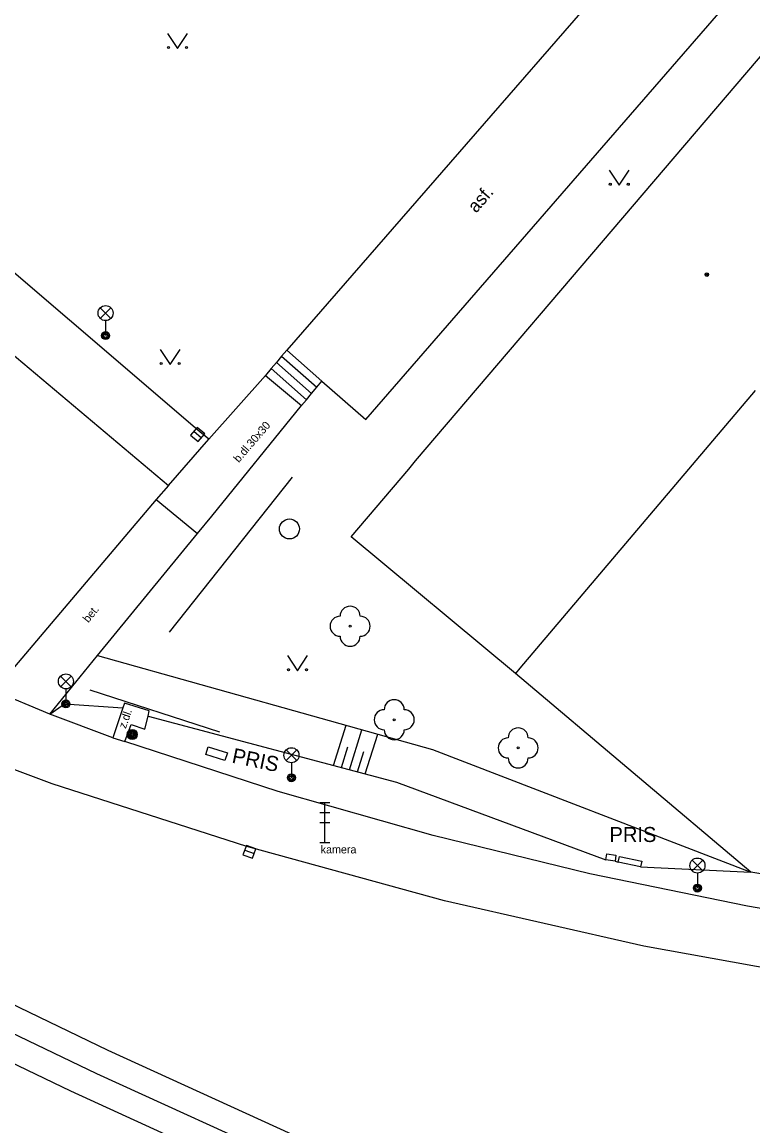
# Model space of a CAD drawing. Extents: x -598932 to -598196, y -1162207 to -1161504.
# Drawn here: x -598545.9 to -598509.4, y -1161999.2 to -1161944.1 of the extents above; entities that cross this region are included whole.
import ezdxf

# ---------------------------------------------------------------- set-up
doc = ezdxf.new("R2010")
doc.units = 0
for name, color, linetype in [('Level 22', 7, 'Continuous'), ('Level 25', 7, 'Continuous'), ('Level 27', 7, 'Continuous'), ('Level 33', 7, 'Continuous'), ('Level 36', 7, 'Continuous'), ('Level 39', 7, 'Continuous'), ('silnoproud - povrch.  znaky a  RIS  skut. velikost', 7, 'Continuous'), ('TM - budovy zdene_ betonove - VP', 7, 'Continuous'), ('TM - CD - osa koleji', 7, 'Continuous'), ('TM - chodniky - VP', 7, 'Continuous'), ('TM - dolni hrana svahu', 7, 'Continuous'), ('TM - horni hrana svahu', 7, 'Continuous'), ('TM - komunikace - VP', 7, 'Continuous'), ('TM - plot zdeny_ ohradni zed - VP', 7, 'Continuous'), ('TM - plot zivy neuzavreny', 7, 'Continuous'), ('TM - popis objektu', 7, 'Continuous'), ('TM - popis povrchu', 7, 'Continuous'), ('TM - poznamka', 7, 'Continuous'), ('TM - rozhrani mezi zpev. plochami mezi sebou - VP', 7, 'Continuous'), ('TM - rozhrani ploch obecne - VP', 7, 'Continuous'), ('TM - schody - VP', 7, 'Continuous'), ('TM - srafovani', 7, 'Continuous')]:
    doc.layers.add(name, color=color, linetype=linetype)

msp = doc.modelspace()

# ---------------------------------------------------------------- linework, layer by layer
at = {"layer": 'Level 22'}
for centre in [(-598529.55, -1161974.25), (-598527.35, -1161978.92), (-598521.16, -1161980.33)]:
    msp.add_circle(centre, 0.05, dxfattribs=at)
for centre, start, end in [((-598529.55, -1161973.75), 0, 180), ((-598530.05, -1161974.25), 90, 270), ((-598529.05, -1161974.25), 270, 90), ((-598529.55, -1161974.75), 180, 0), ((-598527.35, -1161978.42), 0, 180), ((-598527.85, -1161978.92), 90, 270), ((-598526.85, -1161978.92), 270, 90), ((-598527.35, -1161979.42), 180, 0), ((-598521.16, -1161979.83), 0, 180), ((-598521.66, -1161980.33), 90, 270), ((-598520.66, -1161980.33), 270, 90), ((-598521.16, -1161980.83), 180, 0)]:
    msp.add_arc(centre, 0.5, start, end, dxfattribs=at)
at = {"layer": 'Level 25'}
for radius in [0.25, 0.2, 0.15, 0.1, 0.05]:
    msp.add_circle((-598540.43, -1161979.66), radius, dxfattribs=at)
at = {"layer": 'Level 27'}
for p, q in [((-598537.351, -1161964.508), (-598536.969, -1161964.832)), ((-598534.815, -1161985.436), (-598534.345, -1161985.604))]:
    msp.add_line(p, q, dxfattribs=at)
for points in [[(-598537.512, -1161964.699), (-598537.131, -1161965.022), (-598536.808, -1161964.641), (-598537.189, -1161964.318)], [(-598534.899, -1161985.671), (-598534.429, -1161985.839), (-598534.261, -1161985.369), (-598534.731, -1161985.201)]]:
    msp.add_lwpolyline(points, close=True, dxfattribs=at)
msp.add_circle((-598532.58, -1161969.39), 0.5, dxfattribs=at)
at = {"layer": 'Level 33'}
for p, q in [((-598542.025, -1161958.87), (-598541.495, -1161958.34)), ((-598542.025, -1161958.34), (-598541.495, -1161958.87)), ((-598541.76, -1161958.98), (-598541.76, -1161959.73)), ((-598544.005, -1161977.27), (-598543.475, -1161976.74)), ((-598544.005, -1161976.74), (-598543.475, -1161977.27)), ((-598543.74, -1161977.38), (-598543.74, -1161978.13)), ((-598532.745, -1161980.96), (-598532.215, -1161980.43)), ((-598532.745, -1161980.43), (-598532.215, -1161980.96)), ((-598532.48, -1161981.07), (-598532.48, -1161981.82)), ((-598531.07, -1161983.05), (-598530.57, -1161983.05)), ((-598530.82, -1161985.05), (-598530.82, -1161983.05)), ((-598531.07, -1161983.55), (-598530.57, -1161983.55)), ((-598531.07, -1161984.05), (-598530.57, -1161984.05)), ((-598531.07, -1161985.05), (-598530.57, -1161985.05)), ((-598512.475, -1161986.47), (-598511.945, -1161985.94)), ((-598512.475, -1161985.94), (-598511.945, -1161986.47)), ((-598512.21, -1161986.58), (-598512.21, -1161987.33))]:
    msp.add_line(p, q, dxfattribs=at)
for centre, radius in [((-598541.76, -1161958.605), 0.375), ((-598541.76, -1161959.73), 0.2), ((-598541.76, -1161959.73), 0.145), ((-598541.76, -1161959.73), 0.0876), ((-598543.74, -1161977.005), 0.375), ((-598543.74, -1161978.13), 0.2), ((-598543.74, -1161978.13), 0.145), ((-598543.74, -1161978.13), 0.0876), ((-598532.48, -1161980.695), 0.375), ((-598532.48, -1161981.82), 0.2), ((-598532.48, -1161981.82), 0.145), ((-598532.48, -1161981.82), 0.0876), ((-598512.21, -1161986.205), 0.375), ((-598512.21, -1161987.33), 0.2), ((-598512.21, -1161987.33), 0.145), ((-598512.21, -1161987.33), 0.0876)]:
    msp.add_circle(centre, radius, dxfattribs=at)
at = {"layer": 'Level 36'}
for points in [[(-598538.67, -1161944.63), (-598538.17, -1161945.38), (-598537.67, -1161944.63)], [(-598516.61, -1161951.47), (-598516.11, -1161952.22), (-598515.61, -1161951.47)], [(-598539.03, -1161960.42), (-598538.53, -1161961.17), (-598538.03, -1161960.42)], [(-598532.68, -1161975.72), (-598532.18, -1161976.47), (-598531.68, -1161975.72)]]:
    msp.add_lwpolyline(points, dxfattribs=at)
for centre in [(-598538.62, -1161945.33), (-598537.721, -1161945.33), (-598516.56, -1161952.17), (-598515.661, -1161952.17), (-598538.98, -1161961.12), (-598538.081, -1161961.12), (-598532.63, -1161976.42), (-598531.731, -1161976.42)]:
    msp.add_circle(centre, 0.05, dxfattribs=at)
at = {"layer": 'Level 39'}
for radius in [0.09, 0.0398]:
    msp.add_circle((-598511.74, -1161956.68), radius, dxfattribs=at)
at = {"layer": 'silnoproud - povrch.  znaky a  RIS  skut. velikost'}
for points in [[(-598536.63, -1161980.28), (-598535.68, -1161980.58), (-598535.8, -1161980.96), (-598536.75, -1161980.66), (-598536.63, -1161980.28)], [(-598516.78, -1161985.92), (-598516.74, -1161985.62)], [(-598516.32, -1161985.98), (-598516.78, -1161985.92)], [(-598516.74, -1161985.62), (-598516.28, -1161985.68)], [(-598516.28, -1161985.68), (-598516.32, -1161985.98)], [(-598516.16, -1161986.04), (-598516.1, -1161985.75)], [(-598515.05, -1161986.27), (-598516.16, -1161986.04)], [(-598516.1, -1161985.75), (-598514.99, -1161985.98)], [(-598514.99, -1161985.98), (-598515.05, -1161986.27)]]:
    msp.add_lwpolyline(points, dxfattribs=at)
at = {"layer": 'TM - budovy zdene_ betonove - VP'}
for points in [[(-598526.29, -1161965.99), (-598502.49, -1161938.05)], [(-598509.33, -1161962.47), (-598521.08, -1161976.34)], [(-598526.62, -1161966.4), (-598526.29, -1161965.99)], [(-598529.5, -1161969.78), (-598526.62, -1161966.4)], [(-598521.29, -1161976.61), (-598529.5, -1161969.78)], [(-598521.08, -1161976.34), (-598521.29, -1161976.61)]]:
    msp.add_lwpolyline(points, dxfattribs=at)
at = {"layer": 'TM - CD - osa koleji'}
msp.add_lwpolyline([(-598511.97, -1162009.71), (-598522.12, -1162005.55), (-598532.2, -1162001.18), (-598542.19, -1161996.62), (-598552.09, -1161991.87)], dxfattribs=at)
at = {"layer": 'TM - chodniky - VP'}
for points in [[(-598533.59, -1161927.06), (-598521.79, -1161937.04), (-598516.72, -1161941.32), (-598516.36, -1161941.65), (-598532.71, -1161960.46)], [(-598530.97, -1161962), (-598528.77, -1161963.92), (-598504.53, -1161935.99), (-598501.24, -1161936.61)], [(-598536.6, -1161964.9), (-598537.06, -1161964.54), (-598550.08, -1161953.38)], [(-598549.7, -1161957.89), (-598538.62, -1161967.21)], [(-598532.71, -1161960.46), (-598532.97, -1161960.76)], [(-598533.23, -1161961.07), (-598533.49, -1161961.37)], [(-598532.97, -1161960.76), (-598533.23, -1161961.07)], [(-598533.78, -1161961.72), (-598536.6, -1161964.9)], [(-598533.49, -1161961.37), (-598533.78, -1161961.72)], [(-598531.48, -1161962.62), (-598531.22, -1161962.31)], [(-598531.22, -1161962.31), (-598530.97, -1161962)], [(-598531.97, -1161963.22), (-598531.73, -1161962.93)], [(-598531.73, -1161962.93), (-598531.48, -1161962.62)], [(-598536.45, -1161968.75), (-598531.97, -1161963.22)], [(-598538.62, -1161967.21), (-598539.23, -1161967.92), (-598547.34, -1161977.47)], [(-598542.16, -1161975.71), (-598537.17, -1161969.62), (-598536.45, -1161968.75)], [(-598544.55, -1161978.65), (-598542.16, -1161975.71)], [(-598540.89, -1161978.32), (-598541.39, -1161979.82)], [(-598539.64, -1161978.75), (-598539.58, -1161978.48), (-598540.82, -1161978.1), (-598540.89, -1161978.32)], [(-598541.39, -1161979.82), (-598544.55, -1161978.65)], [(-598540.79, -1161980.01), (-598540.49, -1161979.16), (-598539.8, -1161979.4), (-598539.64, -1161978.75)], [(-598509.71, -1161988.23), (-598517.59, -1161986.62), (-598525.41, -1161984.71), (-598533.14, -1161982.51), (-598540.79, -1161980.01)], [(-598492.84, -1161991.17), (-598509.71, -1161988.23)]]:
    msp.add_lwpolyline(points, dxfattribs=at)
at = {"layer": 'TM - dolni hrana svahu'}
msp.add_lwpolyline([(-598542.16, -1161975.71), (-598525.43, -1161980.41), (-598509.55, -1161986.53)], dxfattribs=at)
at = {"layer": 'TM - horni hrana svahu'}
for points in [[(-598544.55, -1161978.65), (-598543.81, -1161978.13), (-598540.89, -1161978.32)], [(-598539.64, -1161978.75), (-598527.23, -1161982.04), (-598516.78, -1161985.92)], [(-598516.32, -1161985.98), (-598516.16, -1161986.04)], [(-598515.05, -1161986.27), (-598509.55, -1161986.53)]]:
    msp.add_lwpolyline(points, dxfattribs=at)
at = {"layer": 'TM - komunikace - VP'}
msp.add_lwpolyline([(-598504.83, -1161992.05), (-598514.88, -1161990.23), (-598524.84, -1161987.97), (-598534.7, -1161985.26), (-598544.42, -1161982.12), (-598553.99, -1161978.54), (-598563.39, -1161974.55)], dxfattribs=at)
at = {"layer": 'TM - plot zdeny_ ohradni zed - VP'}
msp.add_lwpolyline([(-598476.47, -1161992.13), (-598509.55, -1161986.53), (-598521.29, -1161976.61)], dxfattribs=at)
at = {"layer": 'TM - plot zivy neuzavreny'}
for points in [[(-598532.44, -1161966.8), (-598538.58, -1161974.54)], [(-598542.55, -1161977.42), (-598536.08, -1161979.53)]]:
    msp.add_lwpolyline(points, dxfattribs=at)
at = {"layer": 'TM - rozhrani mezi zpev. plochami mezi sebou - VP'}
for points in [[(-598538.62, -1161967.21), (-598536.6, -1161964.9)], [(-598539.23, -1161967.92), (-598537.17, -1161969.62)], [(-598544.55, -1161978.65), (-598547.34, -1161977.47)], [(-598541.39, -1161979.82), (-598540.79, -1161980.01)]]:
    msp.add_lwpolyline(points, dxfattribs=at)
at = {"layer": 'TM - rozhrani ploch obecne - VP'}
for points in [[(-598532.71, -1161960.46), (-598530.97, -1161962)], [(-598533.78, -1161961.72), (-598531.97, -1161963.22)], [(-598511.49, -1162008.5), (-598521.62, -1162004.34), (-598531.67, -1161999.99), (-598541.63, -1161995.44), (-598551.5, -1161990.69)], [(-598515.49, -1162009.7), (-598524.9, -1162005.79), (-598534.23, -1162001.72), (-598543.49, -1161997.48), (-598552.68, -1161993.07)]]:
    msp.add_lwpolyline(points, dxfattribs=at)
at = {"layer": 'TM - schody - VP'}
for points in [[(-598533.23, -1161961.07), (-598531.48, -1161962.62)], [(-598532.97, -1161960.76), (-598531.22, -1161962.31)], [(-598533.49, -1161961.37), (-598531.73, -1161962.93)]]:
    msp.add_lwpolyline(points, dxfattribs=at)
at = {"layer": 'TM - srafovani'}
for points in [[(-598530.38, -1161981.21), (-598529.75, -1161979.2)], [(-598529.58, -1161981.42), (-598528.96, -1161979.42)], [(-598528.8, -1161981.63), (-598528.17, -1161979.64)], [(-598529.98, -1161981.31), (-598529.66, -1161980.27)], [(-598529.19, -1161981.52), (-598528.87, -1161980.51)]]:
    msp.add_lwpolyline(points, dxfattribs=at)

# ---------------------------------------------------------------- texts
at = {"layer": 'TM - popis objektu'}
msp.add_text('PRIS', height=0.75, rotation=348.24, dxfattribs=at).set_placement((-598535.49, -1161981.06))
msp.add_text('PRIS', height=0.75, dxfattribs=at).set_placement((-598516.6, -1161985.03))
at = {"layer": 'TM - popis povrchu'}
for s, height, rotation, p in [('asf.', 0.65, 49, (-598523.26, -1161953.64)), ('b.dl.30x30', 0.4, 49.2885, (-598535.11, -1161966.1)), ('bet.', 0.4, 51, (-598542.62, -1161974.1)), ('z.dl.', 0.4, 71, (-598540.75, -1161979.39))]:
    msp.add_text(s, height=height, rotation=rotation, dxfattribs=at).set_placement(p)
at = {"layer": 'TM - poznamka'}
msp.add_text('kamera', height=0.4, dxfattribs=at).set_placement((-598531.02, -1161985.6))

doc.saveas('drawing.dxf')
